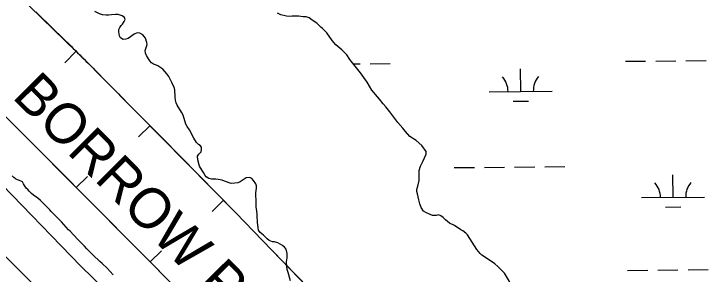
# Model space of a CAD drawing. Extents: x 3146026 to 3183936, y 897894 to 923344.
# Drawn here: x 3171828 to 3172931, y 906304 to 906719 of the extents above; entities that cross this region are included whole.
import ezdxf

# ---------------------------------------------------------------- set-up
doc = ezdxf.new("R2010")
doc.units = 0
for name, color, linetype in [('V-BORW-IDEN', 7, 'Continuous'), ('V-BORW-LINE', 7, 'Continuous'), ('V-LEVE-TOET', 7, 'Continuous'), ('V-SITE-VEGE', 7, 'Continuous'), ('V-SURV-LINE', 7, 'Continuous'), ('V-TOPO-SHOR', 7, 'Continuous'), ('V-WETL-SWMP', 7, 'Continuous')]:
    doc.layers.add(name, color=color, linetype=linetype)

msp = doc.modelspace()

# ---------------------------------------------------------------- linework, layer by layer
at = {"layer": 'V-BORW-LINE'}
for p, q in [((3171862.6, 906721.5), (3171890.6, 906694.4)), ((3171890.6, 906694.4), (3171918.4, 906666.9)), ((3171926.2, 906658.7), (3171908.7, 906640.8)), ((3172004.6, 906580.2), (3172063.1, 906521)), ((3171888.5, 906480.7), (3171820.1, 906549.4)), ((3172043.5, 906540.4), (3172025.7, 906522.8)), ((3172063.1, 906521), (3172121.4, 906461.6)), ((3171956.8, 906412), (3171888.5, 906480.7)), ((3171926.7, 906442), (3171944.4, 906459.6)), ((3172121.4, 906461.6), (3172179.7, 906402.2)), ((3172160.4, 906421.7), (3172142.6, 906404.2)), ((3172025.1, 906343.2), (3171956.8, 906412)), ((3172179.7, 906402.2), (3172237.7, 906342.5)), ((3172093.3, 906274.4), (3172025.1, 906343.2)), ((3172044.2, 906323.9), (3172062, 906341.5)), ((3172237.7, 906342.5), (3172295.6, 906282.7))]:
    msp.add_line(p, q, dxfattribs=at)
for points in [[(3171946, 906639.3), (3171834.5, 906748.6)], [(3172179.7, 906402.2), (3171946, 906639.3)], [(3171751.6, 906617.9), (3172025.1, 906343.2)], [(3172410.8, 906162.5), (3172179.7, 906402.2)], [(3172025.1, 906343.2), (3172297.8, 906067.8)]]:
    msp.add_lwpolyline(points, dxfattribs=at)
msp.add_spline([(3171918.4, 906666.9), (3171946, 906639.3), (3172004.6, 906580.2)], degree=3, dxfattribs=at)
at = {"layer": 'V-LEVE-TOET'}
msp.add_lwpolyline([(3171484.1, 906747.3), (3171544.9, 906708), (3171612.5, 906646.4), (3171792.8, 906462.4), (3171934.1, 906316.9), (3172144.3, 906112.4), (3172408.5, 905842.9), (3172472.2, 905784.8), (3172488.5, 905777.6), (3172496.7, 905779.3), (3172505.5, 905785.9), (3172514.1, 905790.8), (3172519.7, 905791.4), (3172528.5, 905788.5), (3172529.3, 905786.4)], dxfattribs=at)
at = {"layer": 'V-SITE-VEGE'}
for p, q in [((3171968.3, 906717.1), (3171963.6, 906718.5)), ((3171974.5, 906716.5), (3171968.3, 906717.1)), ((3171977.7, 906716.4), (3171974.5, 906716.5)), ((3171982.5, 906717.2), (3171977.7, 906716.4)), ((3171989.3, 906717.6), (3171982.5, 906717.2)), ((3171993.3, 906717.4), (3171989.3, 906717.6)), ((3171999.7, 906715.5), (3171993.3, 906717.4)), ((3172003.2, 906712.7), (3171999.7, 906715.5)), ((3172004.6, 906709.7), (3172003.2, 906712.7)), ((3171998, 906699.8), (3172000, 906702.2)), ((3172000, 906702.2), (3172002.8, 906706.3)), ((3172002.8, 906706.3), (3172004.6, 906709.7)), ((3171994.5, 906689.8), (3171994.6, 906693.4)), ((3171994.6, 906693.4), (3171996, 906696.6)), ((3171996, 906696.6), (3171998, 906699.8)), ((3171995.5, 906683.4), (3171994.5, 906689.8)), ((3171996.9, 906680.2), (3171995.5, 906683.4)), ((3172001.3, 906678), (3171996.9, 906680.2)), ((3172009, 906679.4), (3172005.6, 906678.2)), ((3172018.5, 906686.1), (3172009, 906679.4)), ((3172023.5, 906688.5), (3172018.5, 906686.1)), ((3172027.5, 906687.8), (3172023.5, 906688.5)), ((3172032.6, 906685.2), (3172027.5, 906687.8)), ((3172036.8, 906679.6), (3172032.6, 906685.2)), ((3172039.1, 906673.2), (3172036.8, 906679.6)), ((3172005.6, 906678.2), (3172001.3, 906678)), ((3172036.3, 906660), (3172039.3, 906670)), ((3172039.3, 906670), (3172039.1, 906673.2)), ((3172036.9, 906655.8), (3172036.3, 906660)), ((3172038.6, 906652.2), (3172036.9, 906655.8)), ((3172041.8, 906647.2), (3172038.6, 906652.2)), ((3172043.4, 906643.8), (3172041.8, 906647.2)), ((3172046.1, 906640.6), (3172043.4, 906643.8)), ((3172049.3, 906638.6), (3172046.1, 906640.6)), ((3172052.5, 906637.6), (3172049.3, 906638.6)), ((3172056.3, 906635.8), (3172052.5, 906637.6)), ((3172064.5, 906630.3), (3172056.3, 906635.8)), ((3172070.8, 906623.3), (3172064.5, 906630.3)), ((3172073.8, 906618.7), (3172070.8, 906623.3)), ((3172077.3, 906612.5), (3172073.8, 906618.7)), ((3172078.7, 906609.3), (3172077.3, 906612.5)), ((3172082.5, 906601.5), (3172078.7, 906609.3)), ((3172083.6, 906597.7), (3172082.5, 906601.5)), ((3172083.8, 906586.3), (3172083.6, 906597.7)), ((3172084.5, 906581.3), (3172083.8, 906586.3)), ((3172085.5, 906576.7), (3172084.5, 906581.3)), ((3172086.9, 906573.1), (3172085.5, 906576.7)), ((3172093.8, 906562.1), (3172086.9, 906573.1)), ((3172096.4, 906557.1), (3172093.8, 906562.1)), ((3172101.1, 906542.9), (3172096.4, 906557.1)), ((3172102.9, 906539.1), (3172101.1, 906542.9)), ((3172106.6, 906533.9), (3172102.9, 906539.1)), ((3172113.7, 906520.5), (3172106.6, 906533.9)), ((3172117.9, 906513.7), (3172113.7, 906520.5)), ((3172120.9, 906510.9), (3172117.9, 906513.7)), ((3172123.6, 906509.1), (3172120.9, 906510.9)), ((3172125.6, 906506.3), (3172123.6, 906509.1)), ((3172125.4, 906498.9), (3172126, 906502.5)), ((3172126, 906502.5), (3172125.6, 906506.3)), ((3172119.2, 906492.3), (3172121.8, 906495.3)), ((3172119.9, 906486.5), (3172119.2, 906492.3)), ((3172121.8, 906495.3), (3172125.4, 906498.9)), ((3172122.7, 906476.4), (3172119.9, 906486.5)), ((3172126.6, 906469.1), (3172122.7, 906476.4)), ((3172129, 906465.9), (3172126.6, 906469.1)), ((3172131.4, 906461.5), (3172129, 906465.9)), ((3172133.3, 906459.1), (3172131.4, 906461.5)), ((3172137.3, 906456.7), (3172133.3, 906459.1)), ((3172141.7, 906455.7), (3172137.3, 906456.7)), ((3172148.5, 906455.7), (3172141.7, 906455.7)), ((3172152.1, 906455.2), (3172148.5, 906455.7)), ((3172158.5, 906453.8), (3172152.1, 906455.2)), ((3172162.2, 906452.4), (3172158.5, 906453.8)), ((3172173.2, 906448.7), (3172162.2, 906452.4)), ((3172179, 906449.1), (3172173.2, 906448.7)), ((3172183.4, 906449.9), (3172179, 906449.1)), ((3172187, 906451.3), (3172183.4, 906449.9)), ((3172193.6, 906455.4), (3172187, 906451.3)), ((3172196.8, 906457.8), (3172193.6, 906455.4)), ((3172202.8, 906458.1), (3172196.8, 906457.8)), ((3172206, 906456.5), (3172202.8, 906458.1)), ((3172208.6, 906453.5), (3172206, 906456.5)), ((3172212.1, 906448.1), (3172208.6, 906453.5)), ((3172213.3, 906444.7), (3172212.1, 906448.1)), ((3172212.2, 906433.5), (3172213.1, 906441.3)), ((3172213.1, 906441.3), (3172213.3, 906444.7)), ((3172212.5, 906417.6), (3172212.2, 906433.5)), ((3172212.9, 906411.2), (3172212.5, 906417.6)), ((3172213.7, 906404.4), (3172212.9, 906411.2)), ((3172214.4, 906400), (3172213.7, 906404.4)), ((3172214.4, 906396.8), (3172214.4, 906400)), ((3172215, 906387.2), (3172214.4, 906396.8)), ((3172215.7, 906378), (3172215, 906387.2)), ((3172216.5, 906374.5), (3172215.7, 906378)), ((3172219.1, 906370.8), (3172216.5, 906374.5)), ((3172224.2, 906366.6), (3172219.1, 906370.8)), ((3172226.6, 906364.2), (3172224.2, 906366.6)), ((3172230, 906360.4), (3172226.6, 906364.2)), ((3172233.6, 906358), (3172230, 906360.4)), ((3172238.7, 906356), (3172233.6, 906358)), ((3172241.7, 906355.6), (3172238.7, 906356)), ((3172247.1, 906354.1), (3172241.7, 906355.6)), ((3172254.3, 906349.7), (3172247.1, 906354.1)), ((3172257.7, 906347.1), (3172254.3, 906349.7)), ((3172260.2, 906344.3), (3172257.7, 906347.1)), ((3172261.8, 906337.1), (3172260.2, 906344.3)), ((3172262, 906330.1), (3172261.8, 906337.1)), ((3172261.1, 906324.1), (3172262, 906330.1)), ((3172261.3, 906316.5), (3172261.1, 906324.1)), ((3172261.8, 906311.7), (3172261.3, 906316.5)), ((3172263.6, 906306.7), (3172261.8, 906311.7)), ((3172267.3, 906293.9), (3172263.6, 906306.7))]:
    msp.add_line(p, q, dxfattribs=at)
at = {"layer": 'V-SURV-LINE'}
msp.add_lwpolyline([(3171543.6, 906601.3), (3172818.3, 905332.2)], dxfattribs=at)
at = {"layer": 'V-TOPO-SHOR'}
for points in [[(3172117.9, 906513.7), (3172113.7, 906520.5), (3172106.6, 906533.9), (3172102.9, 906539.1), (3172101.1, 906542.9), (3172096.4, 906557.1), (3172093.8, 906562.1), (3172086.9, 906573.1), (3172085.5, 906576.7), (3172084.5, 906581.3), (3172083.8, 906586.3), (3172083.6, 906597.7), (3172082.5, 906601.5), (3172078.7, 906609.3), (3172077.3, 906612.5), (3172073.8, 906618.7), (3172070.8, 906623.3), (3172064.5, 906630.3), (3172056.3, 906635.8), (3172052.5, 906637.6), (3172049.3, 906638.6), (3172046.1, 906640.6), (3172043.4, 906643.8), (3172041.8, 906647.2), (3172038.6, 906652.2), (3172036.9, 906655.8), (3172036.3, 906660), (3172039.3, 906670), (3172039.1, 906673.2), (3172036.8, 906679.6), (3172032.6, 906685.2), (3172027.5, 906687.8), (3172023.5, 906688.5), (3172018.5, 906686.1), (3172009, 906679.4), (3172005.6, 906678.2), (3172001.3, 906678), (3171996.9, 906680.2), (3171995.5, 906683.4), (3171994.5, 906689.8), (3171994.6, 906693.4), (3171996, 906696.6), (3171998, 906699.8), (3172000, 906702.2), (3172002.8, 906706.3), (3172004.6, 906709.7), (3172003.2, 906712.7), (3171999.7, 906715.5), (3171993.3, 906717.4), (3171989.3, 906717.6), (3171982.5, 906717.2), (3171977.7, 906716.4), (3171974.5, 906716.5), (3171968.3, 906717.1), (3171963.6, 906718.5), (3171956, 906722.2)], [(3172267.3, 906293.9), (3172263.6, 906306.7), (3172261.8, 906311.7), (3172261.3, 906316.5), (3172261.1, 906324.1), (3172262, 906330.1), (3172261.8, 906337.1), (3172260.2, 906344.3), (3172257.7, 906347.1), (3172254.3, 906349.7), (3172247.1, 906354.1), (3172241.7, 906355.6), (3172238.7, 906356), (3172233.6, 906358), (3172230, 906360.4), (3172226.6, 906364.2), (3172224.2, 906366.6), (3172219.1, 906370.8), (3172216.5, 906374.5), (3172215.7, 906378), (3172215, 906387.2), (3172214.4, 906396.8), (3172214.4, 906400), (3172213.7, 906404.4), (3172212.9, 906411.2), (3172212.5, 906417.6), (3172212.2, 906433.5), (3172213.1, 906441.3), (3172213.3, 906444.7), (3172212.1, 906448.1), (3172208.6, 906453.5), (3172206, 906456.5), (3172202.8, 906458.1), (3172196.8, 906457.8), (3172193.6, 906455.4), (3172187, 906451.3), (3172183.4, 906449.9), (3172179, 906449.1), (3172173.2, 906448.7), (3172162.2, 906452.4), (3172158.5, 906453.8), (3172152.1, 906455.2), (3172148.5, 906455.7), (3172141.7, 906455.7), (3172137.3, 906456.7), (3172133.3, 906459.1), (3172131.4, 906461.5), (3172129, 906465.9), (3172126.6, 906469.1), (3172122.7, 906476.4), (3172119.9, 906486.5), (3172119.2, 906492.3), (3172121.8, 906495.3), (3172125.4, 906498.9), (3172126, 906502.5), (3172125.6, 906506.3), (3172123.6, 906509.1), (3172120.9, 906510.9), (3172117.9, 906513.7)], [(3171985.4, 906303.3), (3171975.9, 906313.9), (3171968.1, 906321.2), (3171964.2, 906324.6), (3171953.6, 906334.4), (3171943.5, 906344.4), (3171939.7, 906348.9), (3171936.6, 906352.3), (3171929.6, 906359.1), (3171922.5, 906366.9), (3171917.1, 906372.5), (3171914.5, 906374.9), (3171903.2, 906387.4), (3171896.7, 906393.8), (3171892.1, 906398.8), (3171886.8, 906404.2), (3171884.6, 906406.8), (3171870.1, 906421.7), (3171865.7, 906425.5), (3171859, 906430.1), (3171855.8, 906432.7), (3171851.8, 906436.4), (3171849.6, 906439), (3171847.3, 906441.4), (3171844.5, 906445.2), (3171843.1, 906448), (3171841.1, 906451), (3171836.4, 906453.2), (3171833.2, 906454.2), (3171830.2, 906455.8), (3171827.6, 906458), (3171824.8, 906460.9)]]:
    msp.add_lwpolyline(points, dxfattribs=at)
at = {"layer": 'V-WETL-SWMP'}
for p, q in [((3172367.4, 906638.8), (3172377.9, 906638.9)), ((3172393.9, 906639), (3172425.9, 906639.3)), ((3172799.8, 906643.1), (3172831.8, 906643.4)), ((3172847.8, 906643.5), (3172879.8, 906643.9)), ((3172895.8, 906644), (3172927.8, 906644.3)), ((3172633.2, 906595), (3172632.8, 906631)), ((3172583.2, 906594.5), (3172683.2, 906595.5)), ((3172621.3, 906579.4), (3172645.3, 906579.7)), ((3172527.5, 906473.8), (3172559.5, 906474.2)), ((3172575.5, 906474.3), (3172607.5, 906474.6)), ((3172623.5, 906474.8), (3172655.5, 906475.1)), ((3172671.5, 906475.3), (3172703.5, 906475.6)), ((3172875.3, 906426.6), (3172875, 906462.6)), ((3172825.3, 906426.1), (3172925.3, 906427.1)), ((3172863.5, 906411), (3172887.5, 906411.3)), ((3172803.1, 906310.4), (3172835.1, 906310.7)), ((3172851.1, 906310.9), (3172883.1, 906311.2)), ((3172899.1, 906311.4), (3172931.1, 906311.7))]:
    msp.add_line(p, q, dxfattribs=at)
for points in [[(3172252.1, 906716.8), (3172246.4, 906719.4)], [(3172622.1, 906281.1), (3172607.3, 906305.7), (3172597, 906316.5), (3172592, 906320.8), (3172582.1, 906327.8), (3172571.3, 906334.8), (3172568.7, 906337.2), (3172563.2, 906343.5), (3172548.5, 906366.9), (3172546.2, 906369.5), (3172541, 906373.3), (3172538, 906374.7), (3172527.7, 906381.6), (3172520.1, 906385.2), (3172513.7, 906390.6), (3172509.8, 906394.7), (3172506.4, 906397.1), (3172502.6, 906398.5), (3172498.6, 906397.5), (3172493.2, 906397.7), (3172489.1, 906399.2), (3172482.3, 906402.2), (3172478.9, 906404.6), (3172474.7, 906410.2), (3172472.6, 906416.2), (3172471.2, 906422.6), (3172468.9, 906432.2), (3172468.3, 906436), (3172468.3, 906439.2), (3172470.2, 906446.2), (3172471.6, 906453.1), (3172471.8, 906460.1), (3172471.6, 906463.9), (3172471.9, 906469.3), (3172473.7, 906476.3), (3172477.7, 906483.8), (3172482.8, 906495.2), (3172483, 906499.6), (3172475.9, 906509), (3172467, 906517), (3172457, 906523.5), (3172449.9, 906531.1), (3172445.7, 906536.5), (3172438, 906545.5), (3172425.3, 906562.8), (3172418.6, 906570.6), (3172414.8, 906575.6), (3172408.8, 906582.8), (3172396.6, 906597.2), (3172389, 906609.7), (3172378.5, 906624.5), (3172361.7, 906646.1), (3172356.6, 906653.2), (3172348.6, 906661.2), (3172339.5, 906669.2), (3172333.3, 906676), (3172324.8, 906688.3), (3172322, 906691.7), (3172318.3, 906695.5), (3172315.7, 906697.3), (3172309.3, 906703.9), (3172301.8, 906708.7), (3172296.8, 906712.2), (3172292, 906713.6), (3172287.6, 906713.8), (3172279.9, 906715), (3172275.5, 906714.9), (3172270.1, 906714.9), (3172266.1, 906714.5), (3172261.1, 906714.8), (3172252.1, 906716.8)]]:
    msp.add_lwpolyline(points, dxfattribs=at)
for centre, start, end in [((3172577.9, 906594.9), 359.7992, 41.3429), ((3172688.4, 906596), 139.7992, 181.3429), ((3172820.1, 906426.5), 359.7992, 41.3429), ((3172930.6, 906427.6), 139.7992, 181.3429)]:
    msp.add_arc(centre, 35.2, start, end, dxfattribs=at)

# ---------------------------------------------------------------- texts
at = {"layer": 'V-BORW-IDEN'}
msp.add_text('BORROW PIT', height=64, rotation=314.8741, dxfattribs=at).set_placement((3171823.3, 906585.6))

doc.saveas('drawing.dxf')
